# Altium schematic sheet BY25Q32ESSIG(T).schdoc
size 127 x 101 mm
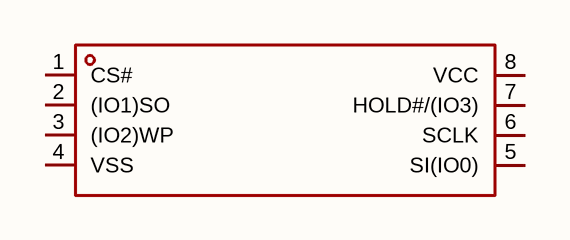
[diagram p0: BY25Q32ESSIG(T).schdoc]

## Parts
U?  by25q32essig(t)  [SOP-8_L5.3-W5.3-P1.27-LS7.9-BL]  (value not drawn)

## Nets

Not connected (* = marked no-connect by the designer): U? 1(CS#) 2((IO1)SO) 3((IO2)WP) 4(VSS) 5(SI(IO0)) 6(SCLK) 7(HOLD#/(IO3)) 8(VCC)

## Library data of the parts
U? = by25q32essig(t): 接口类型:SPI;存储容量:32Mbit;时钟频率(fc):120MHz;; Manufacturer: BOYAMICRO(博雅); AddInBom: yes; ModelId: 72eaeed142424588879d6a198b07ab72; ModelTransform: 207.67675,311.023,0,0,0,0,0,0,0; Interface: SPI; Memory Size: 32Mbit; Clock Frequency: 120MHz; Voltage - Supply: 2.7V~3.6V; Standby Supply Current: 2uA; Program / Erase Cycles: 100000次; Page Programming Time (Tpp): 450us; Block Erase Time(tBE): 180ms; Data Retention - TDR (Year): 20年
